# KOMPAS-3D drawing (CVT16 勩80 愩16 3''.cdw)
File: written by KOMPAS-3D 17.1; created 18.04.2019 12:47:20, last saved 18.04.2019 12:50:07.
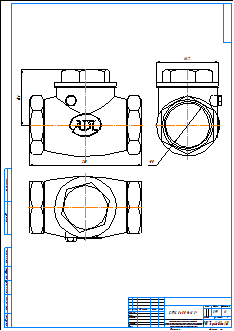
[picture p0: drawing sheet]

Sheet 1: A2, portrait

Title block, sheet 1: name: CVT16 Ду80 Ру16 3''; material: Внимание! Данный продукт является объектом авторского права ООО «Торговый Дом АДЛ». / Запрещается изменение, копирование, распространение / (в том числе путем копирования на другие сайты и ресурсы в Интернете) / или любое иное использование информации и объектов без предварительного / согласия правообладателя (ООО «Торговый Дом АДЛ»).; mass: 3,99; sheets: 1; organisation: ООО "Торговый дом АДЛ"; sheet format: A2

Views: Спереди 1, Проекционный вид 2, Проекционный вид 3
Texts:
  user
Dimensions and other numbers on the sheet: 200; 100; 111,7; 80; 1:1; 1; 3,99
